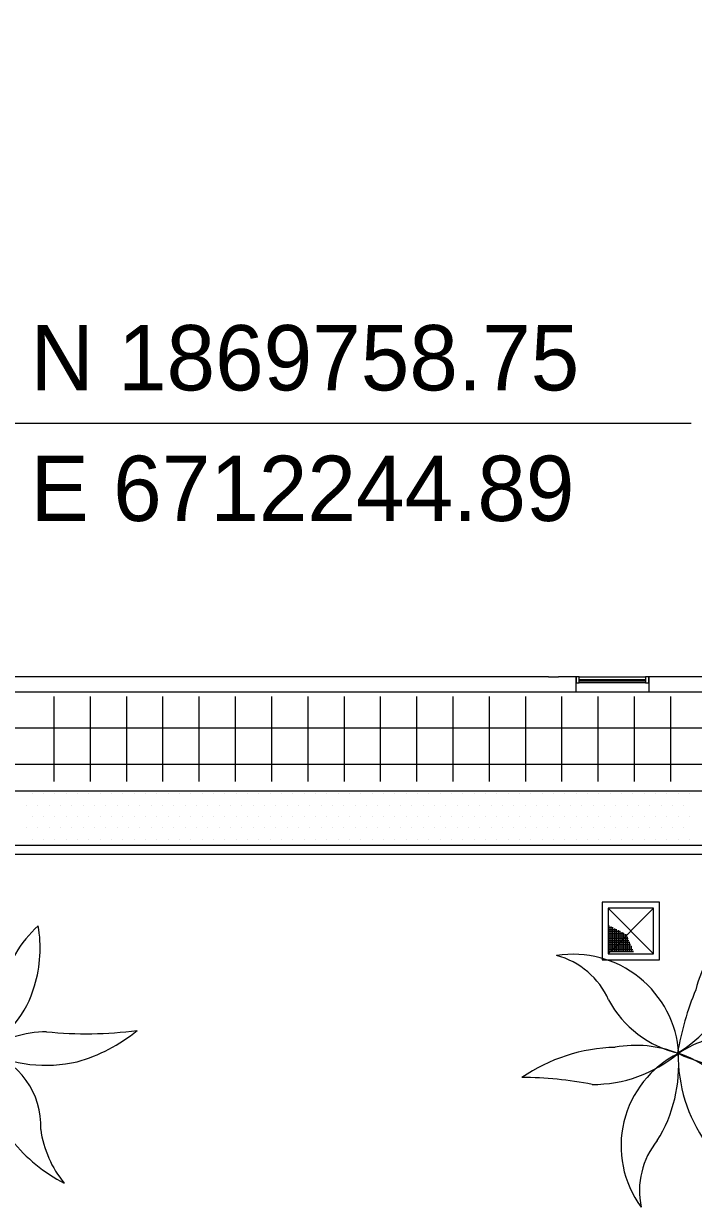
# Model space of a CAD drawing. Extents: x 6712138 to 6712574, y 1869536 to 1870160.
# Drawn here: x 6712269.4 to 6712306.4, y 1869702.8 to 1869768.1 of the extents above; entities that cross this region are included whole.
import ezdxf

# ---------------------------------------------------------------- set-up
doc = ezdxf.new("R2010")
doc.units = 0
for name, color, linetype in [('A-COLS', 7, 'Continuous'), ('A-FLOR-OTLN', 7, 'Continuous'), ('A-FLOR-PATT', 7, 'Continuous'), ('A-GLAZ', 7, 'Continuous'), ('A-GLAZ-FRAM', 7, 'Continuous'), ('A-WALL-FULL-EXT', 7, 'Continuous'), ('I-WALL', 7, 'Continuous'), ('L-Palm', 7, 'Continuous'), ('L-PLNT-PALM', 7, 'Continuous'), ('M-Plan-Misc', 7, 'Continuous')]:
    doc.layers.add(name, color=color, linetype=linetype)

# ---------------------------------------------------------------- blocks, each defined once
blk = doc.blocks.new('PALM_1')
at = {"layer": 'L-Palm'}
for centre, radius, start, end in [((0.3859, 0.0987), 0.3422, 132.6801, 166.8111), ((-0.2114, 0.2856), 0.371, 343.7522, 10.043), ((-0.29, -0.0226), 0.2968, 4.0873, 99.2555), ((-0.393, 0.0561), 0.2213, 24.2552, 75.5182), ((-0.1527, 0.2677), 0.3096, 300.1113, 343.9042), ((0.8252, -0.1374), 0.834, 157.8667, 170.5307), ((0.0708, 0.2901), 0.2986, 208.6354, 257.4748), ((0.1868, -0.2705), 0.3242, 91.3382, 124.0385), ((0.2849, 1.1558), 1.1072, 264.5234, 277.6792), ((0.1358, 0.4172), 0.4657, 286.1702, 309.6262), ((-0.1563, -0.4706), 0.4851, 91.8686, 124.7845), ((-0.1117, -0.3019), 0.3219, 68.8397, 100.8216), ((-0.2364, 0.2825), 0.3726, 270.0402, 310.2895), ((0.1346, -0.2597), 0.2886, 116.7925, 216.8342), ((-0.3946, -0.0377), 0.4007, 328.6183, 5.0923), ((0.4257, -0.0051), 0.4212, 179.4834, 215.787), ((-0.0535, -0.2115), 0.2181, 357.6134, 74.5522), ((0.1756, 0.3541), 0.3946, 244.4343, 283.1777), ((-0.4218, -1.0386), 0.9665, 78.9259, 90.6662), ((0.4639, -0.1765), 0.3027, 188.3856, 219.8245), ((0.1198, -0.3852), 0.2213, 141.1268, 192.3899), ((0.4441, 0.0439), 0.4657, 219.354, 242.8101)]:
    blk.add_arc(centre, radius, start, end, dxfattribs=at)

msp = doc.modelspace()

# ---------------------------------------------------------------- linework, layer by layer
at = {"layer": 'A-COLS'}
msp.add_line((6712260.131, 1869731.271), (6712299.891, 1869731.271), dxfattribs=at)
at = {"layer": 'A-FLOR-OTLN'}
for points in [[(6712251.183, 1869839.781), (6712251.183, 1869722.323), (6712419.14, 1869722.323), (6712419.14, 1869718.864), (6712468.641, 1869718.864), (6712468.641, 1869839.781)], [(6712251.683, 1869839.281), (6712251.683, 1869722.823), (6712419.64, 1869722.823), (6712419.64, 1869719.364), (6712468.141, 1869719.364), (6712468.141, 1869839.281)]]:
    msp.add_lwpolyline(points, close=True, dxfattribs=at)
msp.add_lwpolyline([(6712254.683, 1869836.281), (6712254.683, 1869725.823), (6712428.12, 1869725.823)], dxfattribs=at)
at = {"layer": 'A-FLOR-PATT'}
for p, q in [((6712271.11, 1869726.344), (6712271.11, 1869731.031)), ((6712273.11, 1869726.344), (6712273.11, 1869731.031)), ((6712275.11, 1869726.344), (6712275.11, 1869731.031)), ((6712277.11, 1869726.344), (6712277.11, 1869731.031)), ((6712279.11, 1869726.344), (6712279.11, 1869731.031)), ((6712281.11, 1869726.344), (6712281.11, 1869731.031)), ((6712283.11, 1869726.344), (6712283.11, 1869731.031)), ((6712285.11, 1869726.344), (6712285.11, 1869731.031)), ((6712287.11, 1869726.344), (6712287.11, 1869731.031)), ((6712289.11, 1869726.344), (6712289.11, 1869731.031)), ((6712291.11, 1869726.344), (6712291.11, 1869731.031)), ((6712293.11, 1869726.344), (6712293.11, 1869731.031)), ((6712295.11, 1869726.344), (6712295.11, 1869731.031)), ((6712297.11, 1869726.344), (6712297.11, 1869731.031)), ((6712299.11, 1869726.344), (6712299.11, 1869731.031)), ((6712301.11, 1869726.344), (6712301.11, 1869731.031)), ((6712303.11, 1869726.344), (6712303.11, 1869731.031)), ((6712305.11, 1869726.344), (6712305.11, 1869731.031)), ((6712427.933, 1869729.281), (6712255.204, 1869729.281)), ((6712427.933, 1869727.281), (6712255.204, 1869727.281)), ((6712269.899, 1869725.657), (6712269.899, 1869725.657)), ((6712270.524, 1869725.657), (6712270.524, 1869725.657)), ((6712271.149, 1869725.657), (6712271.149, 1869725.657)), ((6712271.774, 1869725.657), (6712271.774, 1869725.657)), ((6712272.399, 1869725.657), (6712272.399, 1869725.657)), ((6712273.024, 1869725.657), (6712273.024, 1869725.657)), ((6712273.649, 1869725.657), (6712273.649, 1869725.657)), ((6712274.274, 1869725.657), (6712274.274, 1869725.657)), ((6712274.899, 1869725.657), (6712274.899, 1869725.657)), ((6712275.524, 1869725.657), (6712275.524, 1869725.657)), ((6712276.149, 1869725.657), (6712276.149, 1869725.657)), ((6712276.774, 1869725.657), (6712276.774, 1869725.657)), ((6712277.399, 1869725.657), (6712277.399, 1869725.657)), ((6712278.024, 1869725.657), (6712278.024, 1869725.657)), ((6712278.649, 1869725.657), (6712278.649, 1869725.657)), ((6712279.274, 1869725.657), (6712279.274, 1869725.657)), ((6712279.899, 1869725.657), (6712279.899, 1869725.657)), ((6712280.524, 1869725.657), (6712280.524, 1869725.657)), ((6712281.149, 1869725.657), (6712281.149, 1869725.657)), ((6712281.774, 1869725.657), (6712281.774, 1869725.657)), ((6712282.399, 1869725.657), (6712282.399, 1869725.657)), ((6712283.024, 1869725.657), (6712283.024, 1869725.657)), ((6712283.649, 1869725.657), (6712283.649, 1869725.657)), ((6712284.274, 1869725.657), (6712284.274, 1869725.657)), ((6712284.899, 1869725.657), (6712284.899, 1869725.657)), ((6712285.524, 1869725.657), (6712285.524, 1869725.657)), ((6712286.149, 1869725.657), (6712286.149, 1869725.657)), ((6712286.774, 1869725.657), (6712286.774, 1869725.657)), ((6712287.399, 1869725.657), (6712287.399, 1869725.657)), ((6712288.024, 1869725.657), (6712288.024, 1869725.657)), ((6712288.649, 1869725.657), (6712288.649, 1869725.657)), ((6712289.274, 1869725.657), (6712289.274, 1869725.657)), ((6712289.899, 1869725.657), (6712289.899, 1869725.657)), ((6712290.524, 1869725.657), (6712290.524, 1869725.657)), ((6712291.149, 1869725.657), (6712291.149, 1869725.657)), ((6712291.774, 1869725.657), (6712291.774, 1869725.657)), ((6712292.399, 1869725.657), (6712292.399, 1869725.657)), ((6712293.024, 1869725.657), (6712293.024, 1869725.657)), ((6712293.649, 1869725.657), (6712293.649, 1869725.657)), ((6712294.274, 1869725.657), (6712294.274, 1869725.657)), ((6712294.899, 1869725.657), (6712294.899, 1869725.657)), ((6712295.524, 1869725.657), (6712295.524, 1869725.657)), ((6712296.149, 1869725.657), (6712296.149, 1869725.657)), ((6712296.774, 1869725.657), (6712296.774, 1869725.657)), ((6712297.399, 1869725.657), (6712297.399, 1869725.657)), ((6712298.024, 1869725.657), (6712298.024, 1869725.657)), ((6712298.649, 1869725.657), (6712298.649, 1869725.657)), ((6712299.274, 1869725.657), (6712299.274, 1869725.657)), ((6712299.899, 1869725.657), (6712299.899, 1869725.657)), ((6712300.524, 1869725.657), (6712300.524, 1869725.657)), ((6712301.149, 1869725.657), (6712301.149, 1869725.657)), ((6712301.774, 1869725.657), (6712301.774, 1869725.657)), ((6712302.399, 1869725.657), (6712302.399, 1869725.657)), ((6712303.024, 1869725.657), (6712303.024, 1869725.657)), ((6712303.649, 1869725.657), (6712303.649, 1869725.657)), ((6712304.274, 1869725.657), (6712304.274, 1869725.657)), ((6712304.899, 1869725.657), (6712304.899, 1869725.657)), ((6712305.524, 1869725.657), (6712305.524, 1869725.657)), ((6712306.149, 1869725.657), (6712306.149, 1869725.657)), ((6712269.587, 1869725.032), (6712269.587, 1869725.032)), ((6712270.212, 1869725.032), (6712270.212, 1869725.032)), ((6712270.837, 1869725.032), (6712270.837, 1869725.032)), ((6712271.462, 1869725.032), (6712271.462, 1869725.032)), ((6712272.087, 1869725.032), (6712272.087, 1869725.032)), ((6712272.712, 1869725.032), (6712272.712, 1869725.032)), ((6712273.337, 1869725.032), (6712273.337, 1869725.032)), ((6712273.962, 1869725.032), (6712273.962, 1869725.032)), ((6712274.587, 1869725.032), (6712274.587, 1869725.032)), ((6712275.212, 1869725.032), (6712275.212, 1869725.032)), ((6712275.837, 1869725.032), (6712275.837, 1869725.032)), ((6712276.462, 1869725.032), (6712276.462, 1869725.032)), ((6712277.087, 1869725.032), (6712277.087, 1869725.032)), ((6712277.712, 1869725.032), (6712277.712, 1869725.032)), ((6712278.337, 1869725.032), (6712278.337, 1869725.032)), ((6712278.962, 1869725.032), (6712278.962, 1869725.032)), ((6712279.587, 1869725.032), (6712279.587, 1869725.032)), ((6712280.212, 1869725.032), (6712280.212, 1869725.032)), ((6712280.837, 1869725.032), (6712280.837, 1869725.032)), ((6712281.462, 1869725.032), (6712281.462, 1869725.032)), ((6712282.087, 1869725.032), (6712282.087, 1869725.032)), ((6712282.712, 1869725.032), (6712282.712, 1869725.032)), ((6712283.337, 1869725.032), (6712283.337, 1869725.032)), ((6712283.962, 1869725.032), (6712283.962, 1869725.032)), ((6712284.587, 1869725.032), (6712284.587, 1869725.032)), ((6712285.212, 1869725.032), (6712285.212, 1869725.032)), ((6712285.837, 1869725.032), (6712285.837, 1869725.032)), ((6712286.462, 1869725.032), (6712286.462, 1869725.032)), ((6712287.087, 1869725.032), (6712287.087, 1869725.032)), ((6712287.712, 1869725.032), (6712287.712, 1869725.032)), ((6712288.337, 1869725.032), (6712288.337, 1869725.032)), ((6712288.962, 1869725.032), (6712288.962, 1869725.032)), ((6712289.587, 1869725.032), (6712289.587, 1869725.032)), ((6712290.212, 1869725.032), (6712290.212, 1869725.032)), ((6712290.837, 1869725.032), (6712290.837, 1869725.032)), ((6712291.462, 1869725.032), (6712291.462, 1869725.032)), ((6712292.087, 1869725.032), (6712292.087, 1869725.032)), ((6712292.712, 1869725.032), (6712292.712, 1869725.032)), ((6712293.337, 1869725.032), (6712293.337, 1869725.032)), ((6712293.962, 1869725.032), (6712293.962, 1869725.032)), ((6712294.587, 1869725.032), (6712294.587, 1869725.032)), ((6712295.212, 1869725.032), (6712295.212, 1869725.032)), ((6712295.837, 1869725.032), (6712295.837, 1869725.032)), ((6712296.462, 1869725.032), (6712296.462, 1869725.032)), ((6712297.087, 1869725.032), (6712297.087, 1869725.032)), ((6712297.712, 1869725.032), (6712297.712, 1869725.032)), ((6712298.337, 1869725.032), (6712298.337, 1869725.032)), ((6712298.962, 1869725.032), (6712298.962, 1869725.032)), ((6712299.587, 1869725.032), (6712299.587, 1869725.032)), ((6712300.212, 1869725.032), (6712300.212, 1869725.032)), ((6712300.837, 1869725.032), (6712300.837, 1869725.032)), ((6712301.462, 1869725.032), (6712301.462, 1869725.032)), ((6712302.087, 1869725.032), (6712302.087, 1869725.032)), ((6712302.712, 1869725.032), (6712302.712, 1869725.032)), ((6712303.337, 1869725.032), (6712303.337, 1869725.032)), ((6712303.962, 1869725.032), (6712303.962, 1869725.032)), ((6712304.587, 1869725.032), (6712304.587, 1869725.032)), ((6712305.212, 1869725.032), (6712305.212, 1869725.032)), ((6712305.837, 1869725.032), (6712305.837, 1869725.032)), ((6712269.899, 1869724.407), (6712269.899, 1869724.407)), ((6712270.524, 1869724.407), (6712270.524, 1869724.407)), ((6712271.149, 1869724.407), (6712271.149, 1869724.407)), ((6712271.774, 1869724.407), (6712271.774, 1869724.407)), ((6712272.399, 1869724.407), (6712272.399, 1869724.407)), ((6712273.024, 1869724.407), (6712273.024, 1869724.407)), ((6712273.649, 1869724.407), (6712273.649, 1869724.407)), ((6712274.274, 1869724.407), (6712274.274, 1869724.407)), ((6712274.899, 1869724.407), (6712274.899, 1869724.407)), ((6712275.524, 1869724.407), (6712275.524, 1869724.407)), ((6712276.149, 1869724.407), (6712276.149, 1869724.407)), ((6712276.774, 1869724.407), (6712276.774, 1869724.407)), ((6712277.399, 1869724.407), (6712277.399, 1869724.407)), ((6712278.024, 1869724.407), (6712278.024, 1869724.407)), ((6712278.649, 1869724.407), (6712278.649, 1869724.407)), ((6712279.274, 1869724.407), (6712279.274, 1869724.407)), ((6712279.899, 1869724.407), (6712279.899, 1869724.407)), ((6712280.524, 1869724.407), (6712280.524, 1869724.407)), ((6712281.149, 1869724.407), (6712281.149, 1869724.407)), ((6712281.774, 1869724.407), (6712281.774, 1869724.407)), ((6712282.399, 1869724.407), (6712282.399, 1869724.407)), ((6712283.024, 1869724.407), (6712283.024, 1869724.407)), ((6712283.649, 1869724.407), (6712283.649, 1869724.407)), ((6712284.274, 1869724.407), (6712284.274, 1869724.407)), ((6712284.899, 1869724.407), (6712284.899, 1869724.407)), ((6712285.524, 1869724.407), (6712285.524, 1869724.407)), ((6712286.149, 1869724.407), (6712286.149, 1869724.407)), ((6712286.774, 1869724.407), (6712286.774, 1869724.407)), ((6712287.399, 1869724.407), (6712287.399, 1869724.407)), ((6712288.024, 1869724.407), (6712288.024, 1869724.407)), ((6712288.649, 1869724.407), (6712288.649, 1869724.407)), ((6712289.274, 1869724.407), (6712289.274, 1869724.407)), ((6712289.899, 1869724.407), (6712289.899, 1869724.407)), ((6712290.524, 1869724.407), (6712290.524, 1869724.407)), ((6712291.149, 1869724.407), (6712291.149, 1869724.407)), ((6712291.774, 1869724.407), (6712291.774, 1869724.407)), ((6712292.399, 1869724.407), (6712292.399, 1869724.407)), ((6712293.024, 1869724.407), (6712293.024, 1869724.407)), ((6712293.649, 1869724.407), (6712293.649, 1869724.407)), ((6712294.274, 1869724.407), (6712294.274, 1869724.407)), ((6712294.899, 1869724.407), (6712294.899, 1869724.407)), ((6712295.524, 1869724.407), (6712295.524, 1869724.407)), ((6712296.149, 1869724.407), (6712296.149, 1869724.407)), ((6712296.774, 1869724.407), (6712296.774, 1869724.407)), ((6712297.399, 1869724.407), (6712297.399, 1869724.407)), ((6712298.024, 1869724.407), (6712298.024, 1869724.407)), ((6712298.649, 1869724.407), (6712298.649, 1869724.407)), ((6712299.274, 1869724.407), (6712299.274, 1869724.407)), ((6712299.899, 1869724.407), (6712299.899, 1869724.407)), ((6712300.524, 1869724.407), (6712300.524, 1869724.407)), ((6712301.149, 1869724.407), (6712301.149, 1869724.407)), ((6712301.774, 1869724.407), (6712301.774, 1869724.407)), ((6712302.399, 1869724.407), (6712302.399, 1869724.407)), ((6712303.024, 1869724.407), (6712303.024, 1869724.407)), ((6712303.649, 1869724.407), (6712303.649, 1869724.407)), ((6712304.274, 1869724.407), (6712304.274, 1869724.407)), ((6712304.899, 1869724.407), (6712304.899, 1869724.407)), ((6712305.524, 1869724.407), (6712305.524, 1869724.407)), ((6712306.149, 1869724.407), (6712306.149, 1869724.407)), ((6712269.587, 1869723.782), (6712269.587, 1869723.782)), ((6712270.212, 1869723.782), (6712270.212, 1869723.782)), ((6712270.837, 1869723.782), (6712270.837, 1869723.782)), ((6712271.462, 1869723.782), (6712271.462, 1869723.782)), ((6712272.087, 1869723.782), (6712272.087, 1869723.782)), ((6712272.712, 1869723.782), (6712272.712, 1869723.782)), ((6712273.337, 1869723.782), (6712273.337, 1869723.782)), ((6712273.962, 1869723.782), (6712273.962, 1869723.782)), ((6712274.587, 1869723.782), (6712274.587, 1869723.782)), ((6712275.212, 1869723.782), (6712275.212, 1869723.782)), ((6712275.837, 1869723.782), (6712275.837, 1869723.782)), ((6712276.462, 1869723.782), (6712276.462, 1869723.782)), ((6712277.087, 1869723.782), (6712277.087, 1869723.782)), ((6712277.712, 1869723.782), (6712277.712, 1869723.782)), ((6712278.337, 1869723.782), (6712278.337, 1869723.782)), ((6712278.962, 1869723.782), (6712278.962, 1869723.782)), ((6712279.587, 1869723.782), (6712279.587, 1869723.782)), ((6712280.212, 1869723.782), (6712280.212, 1869723.782)), ((6712280.837, 1869723.782), (6712280.837, 1869723.782)), ((6712281.462, 1869723.782), (6712281.462, 1869723.782)), ((6712282.087, 1869723.782), (6712282.087, 1869723.782)), ((6712282.712, 1869723.782), (6712282.712, 1869723.782)), ((6712283.337, 1869723.782), (6712283.337, 1869723.782)), ((6712283.962, 1869723.782), (6712283.962, 1869723.782)), ((6712284.587, 1869723.782), (6712284.587, 1869723.782)), ((6712285.212, 1869723.782), (6712285.212, 1869723.782)), ((6712285.837, 1869723.782), (6712285.837, 1869723.782)), ((6712286.462, 1869723.782), (6712286.462, 1869723.782)), ((6712287.087, 1869723.782), (6712287.087, 1869723.782)), ((6712287.712, 1869723.782), (6712287.712, 1869723.782)), ((6712288.337, 1869723.782), (6712288.337, 1869723.782)), ((6712288.962, 1869723.782), (6712288.962, 1869723.782)), ((6712289.587, 1869723.782), (6712289.587, 1869723.782)), ((6712290.212, 1869723.782), (6712290.212, 1869723.782)), ((6712290.837, 1869723.782), (6712290.837, 1869723.782)), ((6712291.462, 1869723.782), (6712291.462, 1869723.782)), ((6712292.087, 1869723.782), (6712292.087, 1869723.782)), ((6712292.712, 1869723.782), (6712292.712, 1869723.782)), ((6712293.337, 1869723.782), (6712293.337, 1869723.782)), ((6712293.962, 1869723.782), (6712293.962, 1869723.782)), ((6712294.587, 1869723.782), (6712294.587, 1869723.782)), ((6712295.212, 1869723.782), (6712295.212, 1869723.782)), ((6712295.837, 1869723.782), (6712295.837, 1869723.782)), ((6712296.462, 1869723.782), (6712296.462, 1869723.782)), ((6712297.087, 1869723.782), (6712297.087, 1869723.782)), ((6712297.712, 1869723.782), (6712297.712, 1869723.782)), ((6712298.337, 1869723.782), (6712298.337, 1869723.782)), ((6712298.962, 1869723.782), (6712298.962, 1869723.782)), ((6712299.587, 1869723.782), (6712299.587, 1869723.782)), ((6712300.212, 1869723.782), (6712300.212, 1869723.782)), ((6712300.837, 1869723.782), (6712300.837, 1869723.782)), ((6712301.462, 1869723.782), (6712301.462, 1869723.782)), ((6712302.087, 1869723.782), (6712302.087, 1869723.782)), ((6712302.712, 1869723.782), (6712302.712, 1869723.782)), ((6712303.337, 1869723.782), (6712303.337, 1869723.782)), ((6712303.962, 1869723.782), (6712303.962, 1869723.782)), ((6712304.587, 1869723.782), (6712304.587, 1869723.782)), ((6712305.212, 1869723.782), (6712305.212, 1869723.782)), ((6712305.837, 1869723.782), (6712305.837, 1869723.782)), ((6712269.899, 1869723.157), (6712269.899, 1869723.157)), ((6712270.524, 1869723.157), (6712270.524, 1869723.157)), ((6712271.149, 1869723.157), (6712271.149, 1869723.157)), ((6712271.774, 1869723.157), (6712271.774, 1869723.157)), ((6712272.399, 1869723.157), (6712272.399, 1869723.157)), ((6712273.024, 1869723.157), (6712273.024, 1869723.157)), ((6712273.649, 1869723.157), (6712273.649, 1869723.157)), ((6712274.274, 1869723.157), (6712274.274, 1869723.157)), ((6712274.899, 1869723.157), (6712274.899, 1869723.157)), ((6712275.524, 1869723.157), (6712275.524, 1869723.157)), ((6712276.149, 1869723.157), (6712276.149, 1869723.157)), ((6712276.774, 1869723.157), (6712276.774, 1869723.157)), ((6712277.399, 1869723.157), (6712277.399, 1869723.157)), ((6712278.024, 1869723.157), (6712278.024, 1869723.157)), ((6712278.649, 1869723.157), (6712278.649, 1869723.157)), ((6712279.274, 1869723.157), (6712279.274, 1869723.157)), ((6712279.899, 1869723.157), (6712279.899, 1869723.157)), ((6712280.524, 1869723.157), (6712280.524, 1869723.157)), ((6712281.149, 1869723.157), (6712281.149, 1869723.157)), ((6712281.774, 1869723.157), (6712281.774, 1869723.157)), ((6712282.399, 1869723.157), (6712282.399, 1869723.157)), ((6712283.024, 1869723.157), (6712283.024, 1869723.157)), ((6712283.649, 1869723.157), (6712283.649, 1869723.157)), ((6712284.274, 1869723.157), (6712284.274, 1869723.157)), ((6712284.899, 1869723.157), (6712284.899, 1869723.157)), ((6712285.524, 1869723.157), (6712285.524, 1869723.157)), ((6712286.149, 1869723.157), (6712286.149, 1869723.157)), ((6712286.774, 1869723.157), (6712286.774, 1869723.157)), ((6712287.399, 1869723.157), (6712287.399, 1869723.157)), ((6712288.024, 1869723.157), (6712288.024, 1869723.157)), ((6712288.649, 1869723.157), (6712288.649, 1869723.157)), ((6712289.274, 1869723.157), (6712289.274, 1869723.157)), ((6712289.899, 1869723.157), (6712289.899, 1869723.157)), ((6712290.524, 1869723.157), (6712290.524, 1869723.157)), ((6712291.149, 1869723.157), (6712291.149, 1869723.157)), ((6712291.774, 1869723.157), (6712291.774, 1869723.157)), ((6712292.399, 1869723.157), (6712292.399, 1869723.157)), ((6712293.024, 1869723.157), (6712293.024, 1869723.157)), ((6712293.649, 1869723.157), (6712293.649, 1869723.157)), ((6712294.274, 1869723.157), (6712294.274, 1869723.157)), ((6712294.899, 1869723.157), (6712294.899, 1869723.157)), ((6712295.524, 1869723.157), (6712295.524, 1869723.157)), ((6712296.149, 1869723.157), (6712296.149, 1869723.157)), ((6712296.774, 1869723.157), (6712296.774, 1869723.157)), ((6712297.399, 1869723.157), (6712297.399, 1869723.157)), ((6712298.024, 1869723.157), (6712298.024, 1869723.157)), ((6712298.649, 1869723.157), (6712298.649, 1869723.157)), ((6712299.274, 1869723.157), (6712299.274, 1869723.157)), ((6712299.899, 1869723.157), (6712299.899, 1869723.157)), ((6712300.524, 1869723.157), (6712300.524, 1869723.157)), ((6712301.149, 1869723.157), (6712301.149, 1869723.157)), ((6712301.774, 1869723.157), (6712301.774, 1869723.157)), ((6712302.399, 1869723.157), (6712302.399, 1869723.157)), ((6712303.024, 1869723.157), (6712303.024, 1869723.157)), ((6712303.649, 1869723.157), (6712303.649, 1869723.157)), ((6712304.274, 1869723.157), (6712304.274, 1869723.157)), ((6712304.899, 1869723.157), (6712304.899, 1869723.157)), ((6712305.524, 1869723.157), (6712305.524, 1869723.157)), ((6712306.149, 1869723.157), (6712306.149, 1869723.157))]:
    msp.add_line(p, q, dxfattribs=at)
at = {"layer": 'A-GLAZ'}
for p, q in [((6712303.724, 1869731.948), (6712300.058, 1869731.948)), ((6712300.058, 1869731.948), (6712300.058, 1869731.885)), ((6712300.058, 1869731.885), (6712303.724, 1869731.885)), ((6712303.724, 1869731.885), (6712303.724, 1869731.948))]:
    msp.add_line(p, q, dxfattribs=at)
at = {"layer": 'A-GLAZ-FRAM'}
for p, q in [((6712300.058, 1869732.114), (6712299.891, 1869732.114)), ((6712299.891, 1869732.114), (6712299.891, 1869731.781)), ((6712299.891, 1869731.781), (6712300.058, 1869731.781)), ((6712300.058, 1869731.781), (6712300.058, 1869732.114)), ((6712300.058, 1869732.114), (6712303.724, 1869732.114)), ((6712303.724, 1869731.781), (6712300.058, 1869731.781)), ((6712303.891, 1869732.114), (6712303.724, 1869732.114)), ((6712303.724, 1869732.114), (6712303.724, 1869731.781)), ((6712303.724, 1869731.781), (6712303.891, 1869731.781)), ((6712303.891, 1869731.781), (6712303.891, 1869732.114))]:
    msp.add_line(p, q, dxfattribs=at)
at = {"layer": 'A-WALL-FULL-EXT'}
for p, q in [((6712298.37, 1869732.114), (6712260.975, 1869732.114)), ((6712298.37, 1869732.114), (6712298.912, 1869732.114)), ((6712299.891, 1869732.114), (6712298.912, 1869732.114)), ((6712299.891, 1869731.271), (6712299.891, 1869732.114)), ((6712307.891, 1869732.114), (6712303.891, 1869732.114)), ((6712303.891, 1869732.114), (6712303.891, 1869731.271)), ((6712299.891, 1869731.271), (6712428.12, 1869731.271))]:
    msp.add_line(p, q, dxfattribs=at)
at = {"layer": 'I-WALL'}
msp.add_lwpolyline([(6712264.415, 1869746.098), (6712306.24, 1869746.098)], dxfattribs=at)
at = {"layer": 'M-Plan-Misc'}
for p, q in [((6712304.162, 1869716.844), (6712301.662, 1869719.344)), ((6712304.162, 1869719.344), (6712301.662, 1869716.844)), ((6712301.679, 1869718.387), (6712301.731, 1869718.387)), ((6712301.679, 1869718.286), (6712301.928, 1869718.286)), ((6712301.679, 1869718.184), (6712302.124, 1869718.184)), ((6712301.679, 1869718.083), (6712302.32, 1869718.083)), ((6712301.679, 1869717.981), (6712302.516, 1869717.981)), ((6712301.715, 1869716.936), (6712301.715, 1869718.404)), ((6712301.817, 1869716.936), (6712301.817, 1869718.343)), ((6712301.918, 1869716.936), (6712301.918, 1869718.291)), ((6712302.02, 1869716.936), (6712302.02, 1869718.238)), ((6712302.121, 1869716.936), (6712302.121, 1869718.186)), ((6712302.223, 1869716.936), (6712302.223, 1869718.133)), ((6712302.325, 1869716.936), (6712302.325, 1869718.08)), ((6712302.426, 1869716.936), (6712302.426, 1869718.028)), ((6712302.528, 1869716.936), (6712302.528, 1869717.975)), ((6712301.679, 1869717.88), (6712302.679, 1869717.88)), ((6712301.679, 1869717.778), (6712302.721, 1869717.778)), ((6712301.679, 1869717.676), (6712302.762, 1869717.676)), ((6712301.679, 1869717.575), (6712302.803, 1869717.575)), ((6712301.679, 1869717.473), (6712302.845, 1869717.473)), ((6712301.679, 1869717.372), (6712302.886, 1869717.372)), ((6712302.629, 1869716.936), (6712302.629, 1869717.923)), ((6712302.731, 1869716.936), (6712302.731, 1869717.753)), ((6712302.832, 1869716.936), (6712302.832, 1869717.504)), ((6712301.679, 1869717.27), (6712302.928, 1869717.27)), ((6712301.679, 1869717.169), (6712302.969, 1869717.169)), ((6712301.679, 1869717.067), (6712303.011, 1869717.067)), ((6712301.679, 1869716.966), (6712303.052, 1869716.966)), ((6712302.934, 1869716.936), (6712302.934, 1869717.255)), ((6712303.035, 1869716.936), (6712303.035, 1869717.006))]:
    msp.add_line(p, q, dxfattribs=at)
for points in [[(6712304.495, 1869716.51), (6712304.495, 1869719.677), (6712301.329, 1869719.677), (6712301.329, 1869716.51)], [(6712304.162, 1869716.844), (6712304.162, 1869719.344), (6712301.662, 1869719.344), (6712301.662, 1869716.844)]]:
    msp.add_lwpolyline(points, close=True, dxfattribs=at)

# ---------------------------------------------------------------- block references
at = {"layer": 'L-PLNT-PALM', "xscale": 19.685039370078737, "yscale": 19.68503937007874, "rotation": -0.36974722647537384}
for p in [(6712267.16, 1869711.51), (6712305.429, 1869711.378)]:
    msp.add_blockref('PALM_1', p, dxfattribs=at)

# ---------------------------------------------------------------- texts
at = {"layer": 'I-WALL'}
for s, p in [('N 1869758.75', (6712269.815, 1869747.898)), ('E 6712244.89', (6712269.815, 1869740.698))]:
    msp.add_text(s, height=3.6, dxfattribs=at).set_placement(p)

doc.saveas('drawing.dxf')
